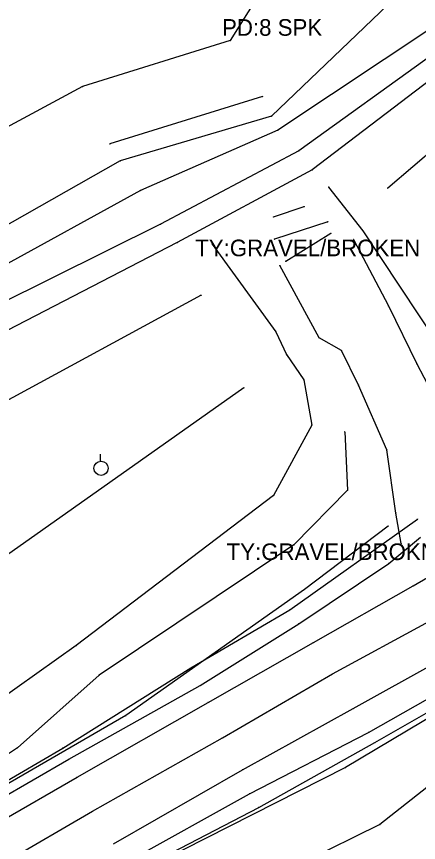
# Model space of a CAD drawing. Extents: x 1419505 to 1434054, y 1956910 to 1968644.
# Drawn here: x 1423305.2 to 1423426, y 1959101.1 to 1959349.3 of the extents above; entities that cross this region are included whole.
import ezdxf

# ---------------------------------------------------------------- set-up
doc = ezdxf.new("R2010")
doc.units = 0
for name, color, linetype in [('S_BREAKLINE', 7, 'Continuous'), ('S_DITCHLINE', 7, 'Continuous'), ('S_DRIVEWAY', 7, 'Continuous'), ('S_DRIVEWAY_ANNOT', 7, 'Continuous'), ('S_EDGE_PAVEMENT', 7, 'Continuous'), ('S_GRD_PT_SYM', 7, 'Continuous'), ('S_PAVEMENT_CROWN', 7, 'Continuous'), ('S_RDW_PT_SYM', 7, 'Continuous'), ('S_SECONDARY_CTL_ANNOT', 7, 'Continuous'), ('S_SHOULDER', 7, 'Continuous'), ('S_UTILITY_POLE', 7, 'Continuous')]:
    doc.layers.add(name, color=color, linetype=linetype)

msp = doc.modelspace()

# ---------------------------------------------------------------- linework, layer by layer
at = {"layer": 'S_BREAKLINE'}
for p, q in [((1423401.5338, 1959393.6317), (1423369.4308, 1959342.0964)), ((1423420.6961, 1959356.6703), (1423381.7956, 1959319.3479)), ((1423369.4308, 1959342.0964), (1423325.0419, 1959328.2905)), ((1423432.3018, 1959332.4447), (1423394.0694, 1959303.2168)), ((1423325.0419, 1959328.2905), (1423242.3606, 1959283.9216)), ((1423379.1074, 1959325.2623), (1423333.2494, 1959311.0613)), ((1423445.3007, 1959322.0911), (1423416.7178, 1959297.7635)), ((1423381.7956, 1959319.3479), (1423336.3566, 1959305.951)), ((1423336.3566, 1959305.951), (1423258.0326, 1959261.5482)), ((1423394.0694, 1959303.2168), (1423353.4707, 1959281.3724)), ((1423409.3454, 1959284.8777), (1423398.9987, 1959298.0945)), ((1423382.4286, 1959289.0949), (1423391.6242, 1959292.2801)), ((1423398.7157, 1959287.6598), (1423382.7046, 1959282.4635)), ((1423386.0678, 1959275.7681), (1423399.6657, 1959284.2106)), ((1423431.5548, 1959251.3445), (1423409.3454, 1959284.8777)), ((1423353.4707, 1959281.3724), (1423268.8403, 1959237.7196)), ((1423363.9874, 1959280.9504), (1423383.1297, 1959254.5897)), ((1423360.6302, 1959265.5784), (1423281.2461, 1959222.5136)), ((1423383.1297, 1959254.5897), (1423386.3109, 1959247.7703)), ((1423386.3109, 1959247.7703), (1423391.4922, 1959240.1028)), ((1423391.4922, 1959240.1028), (1423393.9344, 1959226.5279)), ((1423373.534, 1959237.7496), (1423302.1644, 1959187.3744)), ((1423393.9344, 1959226.5279), (1423382.4416, 1959205.3655)), ((1423403.842, 1959224.4568), (1423404.656, 1959206.9506)), ((1423404.656, 1959206.9506), (1423388.525, 1959190.5186)), ((1423382.4416, 1959205.3655), (1423323.1448, 1959160.2746)), ((1423387.3519, 1959171.0553), (1423425.7314, 1959198.2781)), ((1423416.8598, 1959196.1609), (1423391.6992, 1959177.1637)), ((1423388.525, 1959190.5186), (1423330.0562, 1959151.417)), ((1423391.6992, 1959177.1637), (1423338.0607, 1959139.2833)), ((1423357.585, 1959153.5692), (1423387.3519, 1959171.0553)), ((1423472.7794, 1959164.6929), (1423404.08, 1959123.6312)), ((1423323.1448, 1959160.2746), (1423255.0834, 1959112.1305)), ((1423478.4158, 1959157.2674), (1423414.3837, 1959106.4521)), ((1423330.0562, 1959151.417), (1423305.4456, 1959129.5336)), ((1423319.0565, 1959129.4486), (1423357.585, 1959153.5692)), ((1423412.8916, 1959131.0967), (1423439.3733, 1959146.3467)), ((1423338.0607, 1959139.2833), (1423265.6781, 1959097.3445)), ((1423305.4456, 1959129.5336), (1423263.949, 1959102.2779)), ((1423278.3139, 1959105.8131), (1423319.0565, 1959129.4486)), ((1423377.9933, 1959111.6125), (1423412.8916, 1959131.0967)), ((1423404.08, 1959123.6312), (1423329.1422, 1959085.6858)), ((1423339.3098, 1959091.5662), (1423377.9933, 1959111.6125)), ((1423414.3837, 1959106.4521), (1423338.2538, 1959069.1957))]:
    msp.add_line(p, q, dxfattribs=at)
at = {"layer": 'S_DITCHLINE'}
for p, q in [((1423431.7848, 1959347.1597), (1423383.7177, 1959315.2086)), ((1423430.4317, 1959337.9941), (1423390.0321, 1959308.9862)), ((1423383.7177, 1959315.2086), (1423342.414, 1959297.0324)), ((1423390.0321, 1959308.9862), (1423348.4494, 1959286.9208)), ((1423342.414, 1959297.0324), (1423263.3349, 1959253.5036)), ((1423348.4494, 1959286.9208), (1423264.672, 1959245.3701))]:
    msp.add_line(p, q, dxfattribs=at)
at = {"layer": 'S_DRIVEWAY'}
for p, q in [((1423406.4382, 1959282.2775), (1423416.9888, 1959262.3702)), ((1423396.1595, 1959252.7306), (1423384.3197, 1959274.514)), ((1423416.9888, 1959262.3702), (1423425.4984, 1959244.9341)), ((1423402.8339, 1959248.9233), (1423396.1595, 1959252.7306)), ((1423407.9133, 1959238.5737), (1423402.8339, 1959248.9233)), ((1423425.4984, 1959244.9341), (1423434.41, 1959227.774)), ((1423416.4418, 1959219.0704), (1423407.9133, 1959238.5737)), ((1423419.149, 1959200.1102), (1423416.4418, 1959219.0704)), ((1423420.7811, 1959190.9666), (1423419.149, 1959200.1102))]:
    msp.add_line(p, q, dxfattribs=at)
at = {"layer": 'S_EDGE_PAVEMENT'}
for p, q in [((1423424.3883, 1959178.2548), (1423465.613, 1959202.4093)), ((1423394.4324, 1959161.2367), (1423424.3883, 1959178.2548)), ((1423362.7393, 1959143.1375), (1423394.4324, 1959161.2367)), ((1423406.3952, 1959141.3454), (1423433.8469, 1959156.6184)), ((1423323.4368, 1959120.7161), (1423362.7393, 1959143.1375)), ((1423373.086, 1959122.9022), (1423406.3952, 1959141.3454)), ((1423334.3485, 1959100.7068), (1423373.086, 1959122.9022)), ((1423281.3021, 1959096.4485), (1423323.4368, 1959120.7161))]:
    msp.add_line(p, q, dxfattribs=at)
at = {"layer": 'S_GRD_PT_SYM'}
for points in [[(1423369.4308, 1959342.0964), (1423369.4308, 1959342.1464), (1423369.4308, 1959342.0964), (1423369.3808, 1959342.0964), (1423369.4308, 1959342.0964), (1423369.4308, 1959342.0464), (1423369.4308, 1959342.0964), (1423369.4808, 1959342.0964)], [(1423325.0419, 1959328.2905), (1423325.0419, 1959328.3405), (1423325.0419, 1959328.2905), (1423324.9919, 1959328.2905), (1423325.0419, 1959328.2905), (1423325.0419, 1959328.2405), (1423325.0419, 1959328.2905), (1423325.0919, 1959328.2905)], [(1423379.1074, 1959325.2623), (1423379.1074, 1959325.3123), (1423379.1074, 1959325.2623), (1423379.0574, 1959325.2623), (1423379.1074, 1959325.2623), (1423379.1074, 1959325.2123), (1423379.1074, 1959325.2623), (1423379.1574, 1959325.2623)], [(1423381.7956, 1959319.3479), (1423381.7956, 1959319.3979), (1423381.7956, 1959319.3479), (1423381.7456, 1959319.3479), (1423381.7956, 1959319.3479), (1423381.7956, 1959319.2979), (1423381.7956, 1959319.3479), (1423381.8456, 1959319.3479)], [(1423383.7177, 1959315.2086), (1423383.7177, 1959315.2586), (1423383.7177, 1959315.2086), (1423383.6677, 1959315.2086), (1423383.7177, 1959315.2086), (1423383.7177, 1959315.1586), (1423383.7177, 1959315.2086), (1423383.7677, 1959315.2086)], [(1423333.2494, 1959311.0613), (1423333.2494, 1959311.1113), (1423333.2494, 1959311.0613), (1423333.1994, 1959311.0613), (1423333.2494, 1959311.0613), (1423333.2494, 1959311.0113), (1423333.2494, 1959311.0613), (1423333.2994, 1959311.0613)], [(1423390.0321, 1959308.9862), (1423390.0321, 1959309.0362), (1423390.0321, 1959308.9862), (1423389.9821, 1959308.9862), (1423390.0321, 1959308.9862), (1423390.0321, 1959308.9362), (1423390.0321, 1959308.9862), (1423390.0821, 1959308.9862)], [(1423336.3566, 1959305.951), (1423336.3566, 1959306.001), (1423336.3566, 1959305.951), (1423336.3066, 1959305.951), (1423336.3566, 1959305.951), (1423336.3566, 1959305.901), (1423336.3566, 1959305.951), (1423336.4066, 1959305.951)], [(1423394.0694, 1959303.2168), (1423394.0694, 1959303.2668), (1423394.0694, 1959303.2168), (1423394.0194, 1959303.2168), (1423394.0694, 1959303.2168), (1423394.0694, 1959303.1668), (1423394.0694, 1959303.2168), (1423394.1194, 1959303.2168)], [(1423398.9987, 1959298.0945), (1423398.9987, 1959298.1445), (1423398.9987, 1959298.0945), (1423398.9487, 1959298.0945), (1423398.9987, 1959298.0945), (1423398.9987, 1959298.0445), (1423398.9987, 1959298.0945), (1423399.0487, 1959298.0945)], [(1423416.7178, 1959297.7635), (1423416.7178, 1959297.8135), (1423416.7178, 1959297.7635), (1423416.6678, 1959297.7635), (1423416.7178, 1959297.7635), (1423416.7178, 1959297.7135), (1423416.7178, 1959297.7635), (1423416.7678, 1959297.7635)], [(1423342.414, 1959297.0324), (1423342.414, 1959297.0824), (1423342.414, 1959297.0324), (1423342.364, 1959297.0324), (1423342.414, 1959297.0324), (1423342.414, 1959296.9824), (1423342.414, 1959297.0324), (1423342.464, 1959297.0324)], [(1423391.6242, 1959292.2801), (1423391.6242, 1959292.3301), (1423391.6242, 1959292.2801), (1423391.5742, 1959292.2801), (1423391.6242, 1959292.2801), (1423391.6242, 1959292.2301), (1423391.6242, 1959292.2801), (1423391.6742, 1959292.2801)], [(1423382.4286, 1959289.0949), (1423382.4286, 1959289.1449), (1423382.4286, 1959289.0949), (1423382.3786, 1959289.0949), (1423382.4286, 1959289.0949), (1423382.4286, 1959289.0449), (1423382.4286, 1959289.0949), (1423382.4786, 1959289.0949)], [(1423398.7157, 1959287.6598), (1423398.7157, 1959287.7098), (1423398.7157, 1959287.6598), (1423398.6657, 1959287.6598), (1423398.7157, 1959287.6598), (1423398.7157, 1959287.6098), (1423398.7157, 1959287.6598), (1423398.7657, 1959287.6598)], [(1423348.4494, 1959286.9208), (1423348.4494, 1959286.9708), (1423348.4494, 1959286.9208), (1423348.3994, 1959286.9208), (1423348.4494, 1959286.9208), (1423348.4494, 1959286.8708), (1423348.4494, 1959286.9208), (1423348.4994, 1959286.9208)], [(1423399.6657, 1959284.2106), (1423399.6657, 1959284.2606), (1423399.6657, 1959284.2106), (1423399.6157, 1959284.2106), (1423399.6657, 1959284.2106), (1423399.6657, 1959284.1606), (1423399.6657, 1959284.2106), (1423399.7157, 1959284.2106)], [(1423409.3454, 1959284.8777), (1423409.3454, 1959284.9277), (1423409.3454, 1959284.8777), (1423409.2954, 1959284.8777), (1423409.3454, 1959284.8777), (1423409.3454, 1959284.8277), (1423409.3454, 1959284.8777), (1423409.3954, 1959284.8777)], [(1423353.4707, 1959281.3724), (1423353.4707, 1959281.4224), (1423353.4707, 1959281.3724), (1423353.4207, 1959281.3724), (1423353.4707, 1959281.3724), (1423353.4707, 1959281.3224), (1423353.4707, 1959281.3724), (1423353.5207, 1959281.3724)], [(1423363.9874, 1959280.9504), (1423363.9874, 1959281.0004), (1423363.9874, 1959280.9504), (1423363.9374, 1959280.9504), (1423363.9874, 1959280.9504), (1423363.9874, 1959280.9004), (1423363.9874, 1959280.9504), (1423364.0374, 1959280.9504)], [(1423382.7046, 1959282.4635), (1423382.7046, 1959282.5135), (1423382.7046, 1959282.4635), (1423382.6546, 1959282.4635), (1423382.7046, 1959282.4635), (1423382.7046, 1959282.4135), (1423382.7046, 1959282.4635), (1423382.7546, 1959282.4635)], [(1423386.0678, 1959275.7681), (1423386.0678, 1959275.8181), (1423386.0678, 1959275.7681), (1423386.0178, 1959275.7681), (1423386.0678, 1959275.7681), (1423386.0678, 1959275.7181), (1423386.0678, 1959275.7681), (1423386.1178, 1959275.7681)], [(1423360.6302, 1959265.5784), (1423360.6302, 1959265.6284), (1423360.6302, 1959265.5784), (1423360.5802, 1959265.5784), (1423360.6302, 1959265.5784), (1423360.6302, 1959265.5284), (1423360.6302, 1959265.5784), (1423360.6802, 1959265.5784)], [(1423383.1297, 1959254.5897), (1423383.1297, 1959254.6397), (1423383.1297, 1959254.5897), (1423383.0797, 1959254.5897), (1423383.1297, 1959254.5897), (1423383.1297, 1959254.5397), (1423383.1297, 1959254.5897), (1423383.1797, 1959254.5897)], [(1423386.3109, 1959247.7703), (1423386.3109, 1959247.8203), (1423386.3109, 1959247.7703), (1423386.2609, 1959247.7703), (1423386.3109, 1959247.7703), (1423386.3109, 1959247.7203), (1423386.3109, 1959247.7703), (1423386.3609, 1959247.7703)], [(1423391.4922, 1959240.1028), (1423391.4922, 1959240.1528), (1423391.4922, 1959240.1028), (1423391.4422, 1959240.1028), (1423391.4922, 1959240.1028), (1423391.4922, 1959240.0528), (1423391.4922, 1959240.1028), (1423391.5422, 1959240.1028)], [(1423373.534, 1959237.7496), (1423373.534, 1959237.7996), (1423373.534, 1959237.7496), (1423373.484, 1959237.7496), (1423373.534, 1959237.7496), (1423373.534, 1959237.6996), (1423373.534, 1959237.7496), (1423373.584, 1959237.7496)], [(1423393.9344, 1959226.5279), (1423393.9344, 1959226.5779), (1423393.9344, 1959226.5279), (1423393.8844, 1959226.5279), (1423393.9344, 1959226.5279), (1423393.9344, 1959226.4779), (1423393.9344, 1959226.5279), (1423393.9844, 1959226.5279)], [(1423403.842, 1959224.4568), (1423403.842, 1959224.5068), (1423403.842, 1959224.4568), (1423403.792, 1959224.4568), (1423403.842, 1959224.4568), (1423403.842, 1959224.4068), (1423403.842, 1959224.4568), (1423403.892, 1959224.4568)], [(1423404.656, 1959206.9506), (1423404.656, 1959207.0006), (1423404.656, 1959206.9506), (1423404.606, 1959206.9506), (1423404.656, 1959206.9506), (1423404.656, 1959206.9006), (1423404.656, 1959206.9506), (1423404.706, 1959206.9506)], [(1423382.4416, 1959205.3655), (1423382.4416, 1959205.4155), (1423382.4416, 1959205.3655), (1423382.3916, 1959205.3655), (1423382.4416, 1959205.3655), (1423382.4416, 1959205.3155), (1423382.4416, 1959205.3655), (1423382.4916, 1959205.3655)], [(1423425.7314, 1959198.2781), (1423425.7314, 1959198.3281), (1423425.7314, 1959198.2781), (1423425.6814, 1959198.2781), (1423425.7314, 1959198.2781), (1423425.7314, 1959198.2281), (1423425.7314, 1959198.2781), (1423425.7814, 1959198.2781)], [(1423416.8598, 1959196.1609), (1423416.8598, 1959196.2109), (1423416.8598, 1959196.1609), (1423416.8098, 1959196.1609), (1423416.8598, 1959196.1609), (1423416.8598, 1959196.1109), (1423416.8598, 1959196.1609), (1423416.9098, 1959196.1609)], [(1423388.525, 1959190.5186), (1423388.525, 1959190.5686), (1423388.525, 1959190.5186), (1423388.475, 1959190.5186), (1423388.525, 1959190.5186), (1423388.525, 1959190.4686), (1423388.525, 1959190.5186), (1423388.575, 1959190.5186)], [(1423391.6992, 1959177.1637), (1423391.6992, 1959177.2137), (1423391.6992, 1959177.1637), (1423391.6492, 1959177.1637), (1423391.6992, 1959177.1637), (1423391.6992, 1959177.1137), (1423391.6992, 1959177.1637), (1423391.7492, 1959177.1637)], [(1423387.3519, 1959171.0553), (1423387.3519, 1959171.1053), (1423387.3519, 1959171.0553), (1423387.3019, 1959171.0553), (1423387.3519, 1959171.0553), (1423387.3519, 1959171.0053), (1423387.3519, 1959171.0553), (1423387.4019, 1959171.0553)], [(1423323.1448, 1959160.2746), (1423323.1448, 1959160.3246), (1423323.1448, 1959160.2746), (1423323.0948, 1959160.2746), (1423323.1448, 1959160.2746), (1423323.1448, 1959160.2246), (1423323.1448, 1959160.2746), (1423323.1948, 1959160.2746)], [(1423357.585, 1959153.5692), (1423357.585, 1959153.6192), (1423357.585, 1959153.5692), (1423357.535, 1959153.5692), (1423357.585, 1959153.5692), (1423357.585, 1959153.5192), (1423357.585, 1959153.5692), (1423357.635, 1959153.5692)], [(1423330.0562, 1959151.417), (1423330.0562, 1959151.467), (1423330.0562, 1959151.417), (1423330.0062, 1959151.417), (1423330.0562, 1959151.417), (1423330.0562, 1959151.367), (1423330.0562, 1959151.417), (1423330.1062, 1959151.417)], [(1423338.0607, 1959139.2833), (1423338.0607, 1959139.3333), (1423338.0607, 1959139.2833), (1423338.0107, 1959139.2833), (1423338.0607, 1959139.2833), (1423338.0607, 1959139.2333), (1423338.0607, 1959139.2833), (1423338.1107, 1959139.2833)], [(1423305.4456, 1959129.5336), (1423305.4456, 1959129.5836), (1423305.4456, 1959129.5336), (1423305.3956, 1959129.5336), (1423305.4456, 1959129.5336), (1423305.4456, 1959129.4836), (1423305.4456, 1959129.5336), (1423305.4956, 1959129.5336)], [(1423319.0565, 1959129.4486), (1423319.0565, 1959129.4986), (1423319.0565, 1959129.4486), (1423319.0065, 1959129.4486), (1423319.0565, 1959129.4486), (1423319.0565, 1959129.3986), (1423319.0565, 1959129.4486), (1423319.1065, 1959129.4486)], [(1423412.8916, 1959131.0967), (1423412.8916, 1959131.1467), (1423412.8916, 1959131.0967), (1423412.8416, 1959131.0967), (1423412.8916, 1959131.0967), (1423412.8916, 1959131.0467), (1423412.8916, 1959131.0967), (1423412.9416, 1959131.0967)], [(1423404.08, 1959123.6312), (1423404.08, 1959123.6812), (1423404.08, 1959123.6312), (1423404.03, 1959123.6312), (1423404.08, 1959123.6312), (1423404.08, 1959123.5812), (1423404.08, 1959123.6312), (1423404.13, 1959123.6312)], [(1423377.9933, 1959111.6125), (1423377.9933, 1959111.6625), (1423377.9933, 1959111.6125), (1423377.9433, 1959111.6125), (1423377.9933, 1959111.6125), (1423377.9933, 1959111.5625), (1423377.9933, 1959111.6125), (1423378.0433, 1959111.6125)], [(1423414.3837, 1959106.4521), (1423414.3837, 1959106.5021), (1423414.3837, 1959106.4521), (1423414.3337, 1959106.4521), (1423414.3837, 1959106.4521), (1423414.3837, 1959106.4021), (1423414.3837, 1959106.4521), (1423414.4337, 1959106.4521)]]:
    msp.add_lwpolyline(points, dxfattribs=at)
at = {"layer": 'S_PAVEMENT_CROWN'}
for p, q in [((1423400.1828, 1959151.7261), (1423429.3166, 1959167.6311)), ((1423367.0836, 1959132.5748), (1423400.1828, 1959151.7261)), ((1423328.0091, 1959110.4814), (1423367.0836, 1959132.5748)), ((1423285.2933, 1959085.6888), (1423328.0091, 1959110.4814))]:
    msp.add_line(p, q, dxfattribs=at)
at = {"layer": 'S_RDW_PT_SYM'}
for points in [[(1423406.4382, 1959282.2775), (1423406.4382, 1959282.3275), (1423406.4382, 1959282.2775), (1423406.3882, 1959282.2775), (1423406.4382, 1959282.2775), (1423406.4382, 1959282.2275), (1423406.4382, 1959282.2775), (1423406.4882, 1959282.2775)], [(1423384.3197, 1959274.514), (1423384.3197, 1959274.564), (1423384.3197, 1959274.514), (1423384.2697, 1959274.514), (1423384.3197, 1959274.514), (1423384.3197, 1959274.464), (1423384.3197, 1959274.514), (1423384.3697, 1959274.514)], [(1423416.9888, 1959262.3702), (1423416.9888, 1959262.4202), (1423416.9888, 1959262.3702), (1423416.9388, 1959262.3702), (1423416.9888, 1959262.3702), (1423416.9888, 1959262.3202), (1423416.9888, 1959262.3702), (1423417.0388, 1959262.3702)], [(1423396.1595, 1959252.7306), (1423396.1595, 1959252.7806), (1423396.1595, 1959252.7306), (1423396.1095, 1959252.7306), (1423396.1595, 1959252.7306), (1423396.1595, 1959252.6806), (1423396.1595, 1959252.7306), (1423396.2095, 1959252.7306)], [(1423402.8339, 1959248.9233), (1423402.8339, 1959248.9733), (1423402.8339, 1959248.9233), (1423402.7839, 1959248.9233), (1423402.8339, 1959248.9233), (1423402.8339, 1959248.8733), (1423402.8339, 1959248.9233), (1423402.8839, 1959248.9233)], [(1423425.4984, 1959244.9341), (1423425.4984, 1959244.9841), (1423425.4984, 1959244.9341), (1423425.4484, 1959244.9341), (1423425.4984, 1959244.9341), (1423425.4984, 1959244.8841), (1423425.4984, 1959244.9341), (1423425.5484, 1959244.9341)], [(1423407.9133, 1959238.5737), (1423407.9133, 1959238.6237), (1423407.9133, 1959238.5737), (1423407.8633, 1959238.5737), (1423407.9133, 1959238.5737), (1423407.9133, 1959238.5237), (1423407.9133, 1959238.5737), (1423407.9633, 1959238.5737)], [(1423416.4418, 1959219.0704), (1423416.4418, 1959219.1204), (1423416.4418, 1959219.0704), (1423416.3918, 1959219.0704), (1423416.4418, 1959219.0704), (1423416.4418, 1959219.0204), (1423416.4418, 1959219.0704), (1423416.4918, 1959219.0704)], [(1423419.149, 1959200.1102), (1423419.149, 1959200.1602), (1423419.149, 1959200.1102), (1423419.099, 1959200.1102), (1423419.149, 1959200.1102), (1423419.149, 1959200.0602), (1423419.149, 1959200.1102), (1423419.199, 1959200.1102)], [(1423420.7811, 1959190.9666), (1423420.7811, 1959191.0166), (1423420.7811, 1959190.9666), (1423420.7311, 1959190.9666), (1423420.7811, 1959190.9666), (1423420.7811, 1959190.9166), (1423420.7811, 1959190.9666), (1423420.8311, 1959190.9666)], [(1423417.0388, 1959184.9512), (1423417.0388, 1959185.0012), (1423417.0388, 1959184.9512), (1423416.9888, 1959184.9512), (1423417.0388, 1959184.9512), (1423417.0388, 1959184.9012), (1423417.0388, 1959184.9512), (1423417.0888, 1959184.9512)], [(1423424.3883, 1959178.2548), (1423424.3883, 1959178.3048), (1423424.3883, 1959178.2548), (1423424.3383, 1959178.2548), (1423424.3883, 1959178.2548), (1423424.3883, 1959178.2048), (1423424.3883, 1959178.2548), (1423424.4383, 1959178.2548)], [(1423389.9971, 1959166.809), (1423389.9971, 1959166.859), (1423389.9971, 1959166.809), (1423389.9471, 1959166.809), (1423389.9971, 1959166.809), (1423389.9971, 1959166.759), (1423389.9971, 1959166.809), (1423390.0471, 1959166.809)], [(1423394.4324, 1959161.2367), (1423394.4324, 1959161.2867), (1423394.4324, 1959161.2367), (1423394.3824, 1959161.2367), (1423394.4324, 1959161.2367), (1423394.4324, 1959161.1867), (1423394.4324, 1959161.2367), (1423394.4824, 1959161.2367)], [(1423400.1828, 1959151.7261), (1423400.1828, 1959151.7761), (1423400.1828, 1959151.7261), (1423400.1328, 1959151.7261), (1423400.1828, 1959151.7261), (1423400.1828, 1959151.6761), (1423400.1828, 1959151.7261), (1423400.2328, 1959151.7261)], [(1423360.3702, 1959148.2448), (1423360.3702, 1959148.2948), (1423360.3702, 1959148.2448), (1423360.3202, 1959148.2448), (1423360.3702, 1959148.2448), (1423360.3702, 1959148.1948), (1423360.3702, 1959148.2448), (1423360.4202, 1959148.2448)], [(1423362.7393, 1959143.1375), (1423362.7393, 1959143.1875), (1423362.7393, 1959143.1375), (1423362.6893, 1959143.1375), (1423362.7393, 1959143.1375), (1423362.7393, 1959143.0875), (1423362.7393, 1959143.1375), (1423362.7893, 1959143.1375)], [(1423406.3952, 1959141.3454), (1423406.3952, 1959141.3954), (1423406.3952, 1959141.3454), (1423406.3452, 1959141.3454), (1423406.3952, 1959141.3454), (1423406.3952, 1959141.2954), (1423406.3952, 1959141.3454), (1423406.4452, 1959141.3454)], [(1423410.9445, 1959134.1199), (1423410.9445, 1959134.1699), (1423410.9445, 1959134.1199), (1423410.8945, 1959134.1199), (1423410.9445, 1959134.1199), (1423410.9445, 1959134.0699), (1423410.9445, 1959134.1199), (1423410.9945, 1959134.1199)], [(1423367.0836, 1959132.5748), (1423367.0836, 1959132.6248), (1423367.0836, 1959132.5748), (1423367.0336, 1959132.5748), (1423367.0836, 1959132.5748), (1423367.0836, 1959132.5248), (1423367.0836, 1959132.5748), (1423367.1336, 1959132.5748)], [(1423320.9176, 1959126.1394), (1423320.9176, 1959126.1894), (1423320.9176, 1959126.1394), (1423320.8676, 1959126.1394), (1423320.9176, 1959126.1394), (1423320.9176, 1959126.0894), (1423320.9176, 1959126.1394), (1423320.9676, 1959126.1394)], [(1423373.086, 1959122.9022), (1423373.086, 1959122.9522), (1423373.086, 1959122.9022), (1423373.036, 1959122.9022), (1423373.086, 1959122.9022), (1423373.086, 1959122.8522), (1423373.086, 1959122.9022), (1423373.136, 1959122.9022)], [(1423323.4368, 1959120.7161), (1423323.4368, 1959120.7661), (1423323.4368, 1959120.7161), (1423323.3868, 1959120.7161), (1423323.4368, 1959120.7161), (1423323.4368, 1959120.6661), (1423323.4368, 1959120.7161), (1423323.4868, 1959120.7161)], [(1423375.1741, 1959115.6627), (1423375.1741, 1959115.7127), (1423375.1741, 1959115.6627), (1423375.1241, 1959115.6627), (1423375.1741, 1959115.6627), (1423375.1741, 1959115.6127), (1423375.1741, 1959115.6627), (1423375.2241, 1959115.6627)], [(1423328.0091, 1959110.4814), (1423328.0091, 1959110.5314), (1423328.0091, 1959110.4814), (1423327.9591, 1959110.4814), (1423328.0091, 1959110.4814), (1423328.0091, 1959110.4314), (1423328.0091, 1959110.4814), (1423328.0591, 1959110.4814)]]:
    msp.add_lwpolyline(points, dxfattribs=at)
at = {"layer": 'S_SHOULDER'}
for p, q in [((1423417.0388, 1959184.9512), (1423426.5775, 1959192.8897)), ((1423389.9971, 1959166.809), (1423417.0388, 1959184.9512)), ((1423360.3702, 1959148.2448), (1423389.9971, 1959166.809)), ((1423410.9445, 1959134.1199), (1423437.8082, 1959149.3979)), ((1423320.9176, 1959126.1394), (1423360.3702, 1959148.2448)), ((1423375.1741, 1959115.6627), (1423410.9445, 1959134.1199)), ((1423278.1779, 1959101.4028), (1423320.9176, 1959126.1394)), ((1423337.4357, 1959094.7614), (1423375.1741, 1959115.6627))]:
    msp.add_line(p, q, dxfattribs=at)
at = {"layer": 'S_UTILITY_POLE'}
msp.add_line((1423330.453, 1959215.6803), (1423330.453, 1959217.7883), dxfattribs=at)
msp.add_circle((1423330.5753, 1959213.5391), 2.1268, dxfattribs=at)

# ---------------------------------------------------------------- texts
at = {"layer": 'S_DRIVEWAY_ANNOT'}
for s, p in [('TY:GRAVEL/BROKEN ASPH', (1423358.8791, 1959277.2775)), ('TY:GRAVEL/BROKN ASPHALT', (1423368.3205, 1959185.9666))]:
    msp.add_text(s, height=5, dxfattribs=at).set_placement(p)
at = {"layer": 'S_SECONDARY_CTL_ANNOT'}
msp.add_text('PD:8 SPK', height=5, dxfattribs=at).set_placement((1423366.9413, 1959343.5523))

doc.saveas('drawing.dxf')
